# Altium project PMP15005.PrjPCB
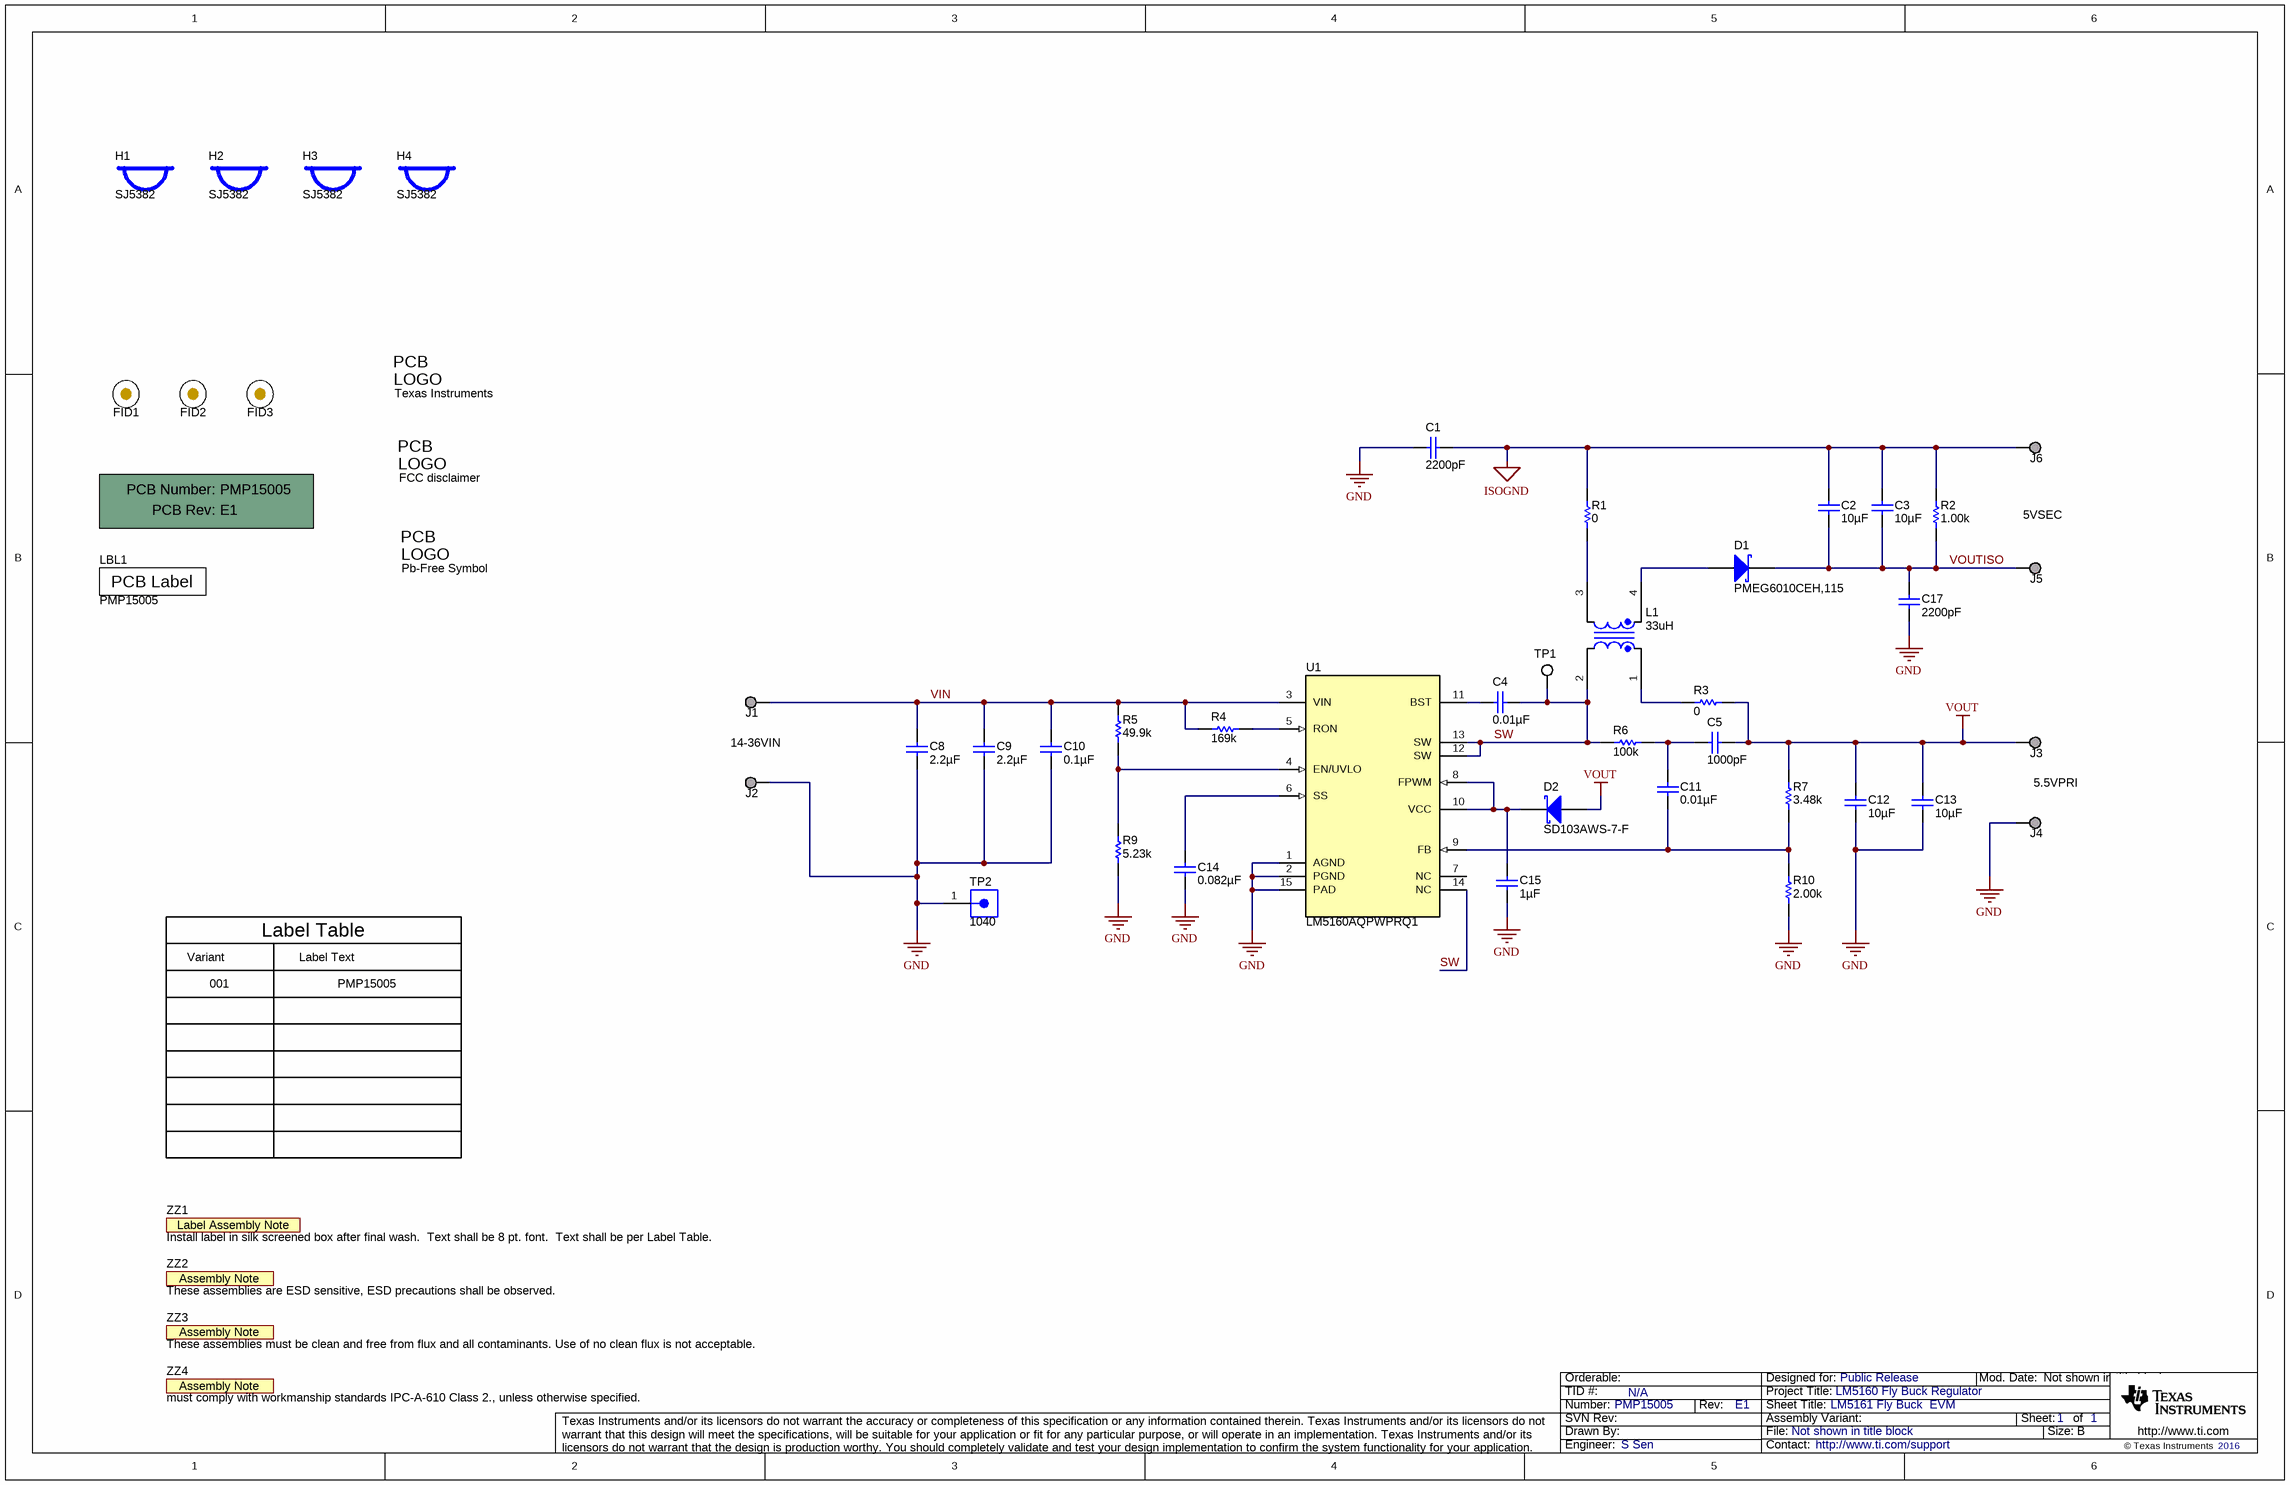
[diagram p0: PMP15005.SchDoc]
CopyrightYear: 2016; PCB_Layout: K Nielson; PCB_Rev: E1; PRJ_Customer: Public Release; PRJ_Engineer: S Sen; PRJ_Number: PMP15005; PRJ_Title: LM5160 Fly Buck Regulator; SCH_Rev: E1; TechSupport: http://www.ti.com/support; TID: N/A
1 sheet, 51 parts. Net scope: global (net labels, ports and power ports of the same name join across sheets).
Board file: PMP15005.PcbDoc

## Sheet PMP15005.SchDoc: LM5161 Fly Buck  EVM
size 431 x 279 mm; Date: Not shown in title block; ApprovedBy: Not shown in title block; CheckedBy: Not shown in title block; Author: Not shown in title block; CompanyName: Not shown in title block; Engineer: Not shown in title block; Organization: Not shown in title block; Address1: Not shown in title block; Address2: Not shown in title block; Address3: Not shown in title block; Address4: Not shown in title block; DocumentNumber: 1; Revision: Use project parameter SCH_Rev; SheetNumber: 1; SheetTotal: 1; PageSetup: Record=PageOptions¦CenterHorizontal=True¦CenterVertical=True¦PrintScale=1.00¦XCorrection=1.00¦YCorrection=1.00¦PrintKind=0¦BorderSize=5000000¦LeftOffset=0¦BottomOffset=0¦Orientation=2¦PaperLength=1000¦PaperWidth=1000¦Scale=100¦PaperSource=15¦PrintQuality=600¦MediaType=1¦DitherType=10¦PaperKind=Letter¦PrintScaleMode=1

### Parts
!PCB1  Printed Circuit Board  (value not drawn)  (mechanical)
C1  ValueDisplayed: 2200pF  [1210_280]  (hidden comment: 202S41W222KV4E)
C2  ValueDisplayed: 10µF  [1206_190]  (hidden comment: C3216X7R1E106M160AE)
C3  ValueDisplayed: 10µF  [1206_190]  (hidden comment: C3216X7R1E106M160AE)
C4  ValueDisplayed: 0.01µF  [0603L]  (hidden comment: GRM188R71C103KA01D)
C5  ValueDisplayed: 1000pF  [0603L]  (hidden comment: GRM188R72A102KA01D)
C8  ValueDisplayed: 2.2µF  [1206_190]  (hidden comment: GRM31CR72A225KA73L)
C9  ValueDisplayed: 2.2µF  [1206_190]  (hidden comment: GRM31CR72A225KA73L)
C10  ValueDisplayed: 0.1µF  [0603L]  (hidden comment: GRM188R72A104KA35D)
C11  ValueDisplayed: 0.01µF  [0603L]  (hidden comment: C0603X103K5RACTU)
C12  ValueDisplayed: 10µF  [1206_190]  (hidden comment: C3216X7R1E106M160AE)
C13  ValueDisplayed: 10µF  [1206_190]  (hidden comment: C3216X7R1E106M160AE)
C14  ValueDisplayed: 0.082µF  [0603L]  (hidden comment: 0603YC823KAT2A)
C15  ValueDisplayed: 1µF  [0603L]  (hidden comment: C1608X7R1C105K)
C17  ValueDisplayed: 2200pF  [1210_280]  (hidden comment: 202S41W222KV4E)
D1  PMEG6010CEH,115  [SOD-123F]
D2  SD103AWS-7-F  [sod-323]
FID1  Fiducial  [Fiducial10-20]  (value not drawn)
FID2  Fiducial  [Fiducial10-20]  (value not drawn)
FID3  Fiducial  [Fiducial10-20]  (value not drawn)
H1  SJ5382  [3M_SJ5382]
H2  SJ5382  [3M_SJ5382]
H3  SJ5382  [3M_SJ5382]
H4  SJ5382  [3M_SJ5382]
J1  Suggest using a net name here  [Keystone1573-2]  (value not drawn)
J2  Suggest using a net name here  [Keystone1573-2]  (value not drawn)
J3  Suggest using a net name here  [Keystone1573-2]  (value not drawn)
J4  Suggest using a net name here  [Keystone1573-2]  (value not drawn)
J5  Suggest using a net name here  [Keystone1573-2]  (value not drawn)
J6  Suggest using a net name here  [Keystone1573-2]  (value not drawn)
L1  33uH  [LPR8035V-223x]
LBL1  PMP15005  [Label_650x200]
Logo1  Texas Instruments  [TI_Stacked_Overlay_Small]  (no BOM)
Logo2  FCC disclaimer  [FCC_disclaimer]  (no BOM)
Logo3  Pb-Free Symbol  [Pb-Free_Overlay_Small]  (no BOM)
R1  value 0  [0805_HV]  (hidden comment: CRCW08050000Z0EA)
R2  ValueDisplayed: 1.00k  [0805_HV]  (hidden comment: CRCW08051K00FKEA)
R3  value 0  [0805_HV]  (hidden comment: CRCW08050000Z0EA)
R4  ValueDisplayed: 169k  [0603L]  (hidden comment: CRCW0603169KFKEA)
R5  ValueDisplayed: 49.9k  [0603L]  (hidden comment: CRCW060349K9FKEA)
R6  ValueDisplayed: 100k  [0603L]  (hidden comment: CRCW0603100KFKEA)
R7  ValueDisplayed: 3.48k  [0603L]  (hidden comment: CRCW06033K48FKEA)
R9  ValueDisplayed: 5.23k  [0603L]  (hidden comment: CRCW06035K23FKEA)
R10  value 2.00k  [0603L]  (hidden comment: CRCW06032K00FKEA)
TP1  5015  [Testpoint_Keystone_Miniature]  (value not drawn)
TP2  1040  [CONN_1040]
U1  LM5160AQPWPRQ1  [PWP0014A_N]
ZZ1  Install label in silk screened box after final wash.  Text shall be 8 pt. font.  Text shall be per Label Table.  [AssemblyNoteLabel]  (no BOM)
ZZ2  These assemblies are ESD sensitive, ESD precautions shall be observed.  [AssemblyNote]  (no BOM)
ZZ3  These assemblies must be clean and free from flux and all contaminants. Use of no clean flux is not acceptable.  [AssemblyNote]  (no BOM)
ZZ4  must comply with workmanship standards IPC-A-610 Class 2., unless otherwise specified.  [AssemblyNote]  (no BOM)

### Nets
GND: C1.1 C8.2 C9.2 C10.2 C12.2 C13.2 C14.2 C15.2 C17.1 J2.1 J4.1 R9.1 R10.1 TP2.1 U1.1(AGND) U1.2(PGND) U1.15(PAD)
ISOGND: C1.2 C2.1 C3.1 J6.1 R1.2 R2.2
VOUT: C5.1 C12.1 C13.1 D2.2(A) J3.1 R3.1 R7.2
SW: C4.1 L1.2 R6.1 TP1.1 U1.12(SW) U1.13(SW) U1.14(NC)
VIN: C8.1 C9.1 C10.1 J1.1 R4.1 R5.2 U1.3(VIN)
VOUTISO: C2.2 C3.2 C17.2 D1.1(K) J5.1 R2.1
NetC4_2: C4.2 U1.11(BST)
NetC5_2: C5.2 C11.1 R6.2
NetC11_2: C11.2 R7.1 R10.2 U1.9(FB)
NetC14_1: C14.1 U1.6(SS)
NetC15_1: C15.1 D2.1(K) U1.8(FPWM) U1.10(VCC)
NetD1_2: D1.2(A) L1.4
NetL1_1: L1.1 R3.2
NetL1_3: L1.3 R1.1
NetR4_2: R4.2 U1.5(RON)
NetR5_1: R5.1 R9.2 U1.4(EN/UVLO)

Not connected (* = marked no-connect by the designer): U1 7(NC)

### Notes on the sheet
- 5VSEC
- 14-36VIN
- 5.5VPRI
- Variant
- Label Table
- Label Text
- 001
- PMP15005

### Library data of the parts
!PCB1 = PCB: Manufacturer: Any; PartNumber: PMP15005; SymbolCreator: a0412235
C1 C17 = 202S41W222KV4E: CAP, CERM, 2200 pF, 2000 V, +/- 10%, X7R, 1210; Manufacturer: Johanson Technology; Polarized: N; CompType: Capacitor; Value: 2200pF; U/M: EA; Cap_F: 0.0000000022; Tolerance_%: 10; Value1: Unknown; VDC_V: 2000; Value2: 2000V; TaMin_C: -55; TaMax_C: 125; Cap_Case: 1210; AEC Category: Q200
C2 C3 C12 C13 = C3216X7R1E106M160AE: CAP, CERM, 10 µF, 25 V, +/- 20%, X7R, 1206_190; Manufacturer: TDK; Polarized: N; CompType: Capacitor; Value: 10uF; U/M: EA; Cap_F: 0.00001; Tolerance_%: 20; Value1: Unknown; VDC_V: 25; Value2: 25V; TaMin_C: -55; TaMax_C: 125; Cap_Case: 1206; AEC Category: Q200
C4 = GRM188R71C103KA01D: CAP, CERM, 0.01uF, 16V, +/-10%, X7R, 0603; Manufacturer: MuRata; Polarized: N; CompType: Capacitor; U/M: EA; Cap_F: 0.00000001; Tolerance_%: 10; Value1: Unknown; VDC_V: 16; TaMin_C: -55; TaMax_C: 125; Cap_Case: 0603
C5 = GRM188R72A102KA01D: CAP, CERM, 1000 pF, 100 V, +/- 10%, X7R, 0603; Manufacturer: MuRata; Polarized: N; CompType: Capacitor; Value: 1000pF; U/M: EA; Cap_F: 0.000000001; Tolerance_%: 10; Value1: Unknown; VDC_V: 100; Value2: 100V; TaMin_C: -55; TaMax_C: 125; Cap_Case: 0603
C8 C9 = GRM31CR72A225KA73L: CAP, CERM, 2.2 µF, 100 V, +/- 10%, X7R, 1206_190; Manufacturer: MuRata; Polarized: N; CompType: Capacitor; Value: 2.2uF; U/M: EA; VDC_V: 100; Cap_F: 0.0000022; Tolerance_%: 10; Value1: Unknown; Value2: 100V; TaMin_C: -55; TaMax_C: 125; Cap_Case: 1206; AEC Category: Q200
C10 = GRM188R72A104KA35D: CAP, CERM, 0.1 µF, 100 V, +/- 10%, X7R, 0603; Manufacturer: MuRata; Polarized: N; CompType: Capacitor; Value: 0.1uF; U/M: EA; Cap_F: 0.0000001; Tolerance_%: 10; Value1: Unknown; VDC_V: 100; Value2: 100V; TaMin_C: -55; TaMax_C: 125; Cap_Case: 0603; AEC Category: Q200
C11 = C0603X103K5RACTU: CAP, CERM, 0.01 µF, 50 V, +/- 10%, X7R, 0603; Manufacturer: Kemet; Polarized: N; CompType: Capacitor; Value: 0.01uF; U/M: EA; Cap_F: 0.00000001; Tolerance_%: 10; Value1: Unknown; VDC_V: 50; Value2: 50V; TaMin_C: -55; TaMax_C: 125; Cap_Case: 0603; AEC Category: Q200
C14 = 0603YC823KAT2A: CAP, CERM, 0.082 µF, 16 V, +/- 10%, X7R, 0603; Manufacturer: AVX; Polarized: N; CompType: Capacitor; Value: 0.082uF; U/M: EA; Cap_F: 0.000000082; Tolerance_%: 10; ESR_ohm: 0.042; Value1: 0.042 ohm; VDC_V: 16; Value2: 16V; TaMin_C: -55; TaMax_C: 125; Cap_Case: 0603
C15 = C1608X7R1C105K: CAP, CERM, 1uF, 16V, +/-10%, X7R, 0603; Manufacturer: TDK; Polarized: N; CompType: Capacitor; U/M: EA; Cap_F: 0.000001; Tolerance_%: 10; ESR_Ohm: 0.0057; Value1: 0.0057 ohm; VDC_V: 16; TaMin_C: -55; TaMax_C: 125; Cap_Case: 0603
D1 = PMEG6010CEH,115: Diode, Schottky, 60 V, 1 A, SOD-123F; Manufacturer: NXP Semiconductor; Value: 60V; U/M: EA; Vf_V: 0.57; Value1: 1A; Value2: 0.57V; Io_A: 1; Vr_V: 60; TJmax_C: 150; SizeAreaWB_mm2: 11.7; SizeArea_mm2: 5.6; SizeX_mm: 3.5; SizeY_mm: 1.6; SizeZ_mm: 1.1; AEC Category: Q101
D2 = SD103AWS-7-F: Diode, Schottky, 40 V, 0.35 A, SOD-323; Manufacturer: Diodes Inc.; Value: 40V; U/M: EA; Vf_V: 0.55; Value1: 0.35A; Value2: 0.55V; Io_A: 0.35; Vr_V: 40; AEC Category: Q101
FID1-FID3 = Fiducial: Fiducial mark.  There is nothing to buy or mount.; SymbolCreator: codlsc
H1-H4 = SJ5382: Bumpon, Hemisphere, 0.25 X 0.075, Clear; Manufacturer: 3M; SymbolCreator: a0412235
J1-J6 = 1573-2: Terminal, Turret, TH, Double; Manufacturer: Keystone; CompType: Turret Terminal
L1 = LPR8035V-333MR: Coupled inductor, 33 µH, 0.75 A, 0.2 ohm, SMD; Manufacturer: Coilcraft; SymbolVersion: use current date i.e. 2008-05-20; SymbolCreator: Use a-id; U/M: EA, IN, or GM
LBL1 = THT-13-457-10: Thermal Transfer Printable Labels, 1.250" W x 0.250" H - 10,000 per roll; Manufacturer: Brady; SymbolCreator: a0412235; CompType: Label
Logo1 = TI_Logo: Texas Instrument Corporate Signature; SymbolCreator: a0412235
Logo2 = FCC_disclaimer: SymbolCreator: codlsc
Logo3 = Pb-Free: SymbolCreator: a0412235
R1 R3 = CRCW08050000Z0EA: RES, 0 ohm, 5%, 0.125W, 0805; Manufacturer: Vishay-Dale; CompType: Resistor; Value_Code: 0000; Tolerance_%: 5; Power_W: 0.125; VDC_V: 150; TempCo: 200 ppm/C; EIA_Code: E24; U/M: EA
R2 = CRCW08051K00FKEA: RES, 1.00 k, 1%, 0.125 W, 0805; Manufacturer: Vishay-Dale; CompType: Resistor; Value: 1.00k; Res_ohm: 1000; Value_Code: 1k00; Tolerance_%: 1; Power_W: 0.125; Value2: 0.125W; VDC_V: 150; TempCo: 100 ppm/C; EIA_Code: E96; U/M: EA; AEC Category: Q200
R4 = CRCW0603169KFKEA: RES, 169 k, 1%, 0.1 W, 0603; Manufacturer: Vishay-Dale; CompType: Resistor; Value: 169k; Res_ohm: 169000; Tolerance_%: 1; Power_W: 0.1; Value2: 0.1W; VDC_V: 75; TempCo: 100 ppm/C; EIA_Code: E96; U/M: EA; AEC Category: Q200; SizeArea_mm2: 1.28; SizeX_mm: 1.6; SizeY_mm: 0.8
R5 = CRCW060349K9FKEA: RES, 49.9 k, 1%, 0.1 W, 0603; Manufacturer: Vishay-Dale; CompType: Resistor; Value: 49.9k; Res_ohm: 49900; Value_Code: 49k9; Tolerance_%: 1; Power_W: 0.1; Value2: 0.1W; VDC_V: 75; TempCo: 100 ppm/C; EIA_Code: E96; U/M: EA; AEC Category: Q200
R6 = CRCW0603100KFKEA: RES, 100 k, 1%, 0.1 W, 0603; Manufacturer: Vishay-Dale; CompType: Resistor; Value: 100k; Res_ohm: 100000; Tolerance_%: 1; Power_W: 0.1; Value2: 0.1W; VDC_V: 75; TempCo: 100 ppm/C; EIA_Code: E96; U/M: EA
R7 = CRCW06033K48FKEA: RES, 3.48 k, 1%, 0.1 W, 0603; Manufacturer: Vishay-Dale; CompType: Resistor; Value: 3.48k; Res_ohm: 3480; Value_Code: 3k48; Tolerance_%: 1; Power_W: 0.1; Value2: 0.1W; VDC_V: 75; TempCo: 100 ppm/C; EIA_Code: E96; U/M: EA; AEC Category: Q200; SizeArea_mm2: 1.28; SizeX_mm: 1.6; SizeY_mm: 0.8
R9 = CRCW06035K23FKEA: RES, 5.23 k, 1%, 0.1 W, 0603; Manufacturer: Vishay-Dale; CompType: Resistor; Value: 5.23k; Res_ohm: 5230; Value_Code: 5k23; Tolerance_%: 1; Power_W: 0.1; Value2: 0.1W; VDC_V: 75; TempCo: 100 ppm/C; EIA_Code: E96; U/M: EA; AEC Category: Q200
R10 = CRCW06032K00FKEA: RES, 2.00k ohm, 1%, 0.1W, 0603; Manufacturer: Vishay-Dale; CompType: Resistor; Res_ohm: 2000; Value_Code: 2k00; Tolerance_%: 1; Power_W: 0.1; VDC_V: 75; TempCo: 100 ppm/C; EIA_Code: E96; U/M: EA
TP1 = 5015: Test Point, Miniature, SMT; Manufacturer: Keystone; CompType: Test Point Loop
TP2 = 1040: TEST POINT SLOTTED .118", TH; Manufacturer: Keystone; SymbolCreator: a0412235; CompType: Test Point Loop; U/M: EA
U1 = LM5160AQPWPRQ1: Wide Input 65V, 1.5A Synchronous Step-Down DC-DC Converter, PWP0014A; Alternate PartNumber: LM5160AQPWPTQ1; Manufacturer: Texas Instruments; SymbolCreator: a0411947; CompType: IC; U/M: EA
ZZ1 = AssemblyNoteLabel: SymbolCreator: a0412235
ZZ2-ZZ4 = AssemblyNote: SymbolCreator: codlsc

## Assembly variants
001: not fitted C17 D2 FID1 FID2 FID3 LBL1 R9
002: not fitted C17 D2 FID1 FID2 FID3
